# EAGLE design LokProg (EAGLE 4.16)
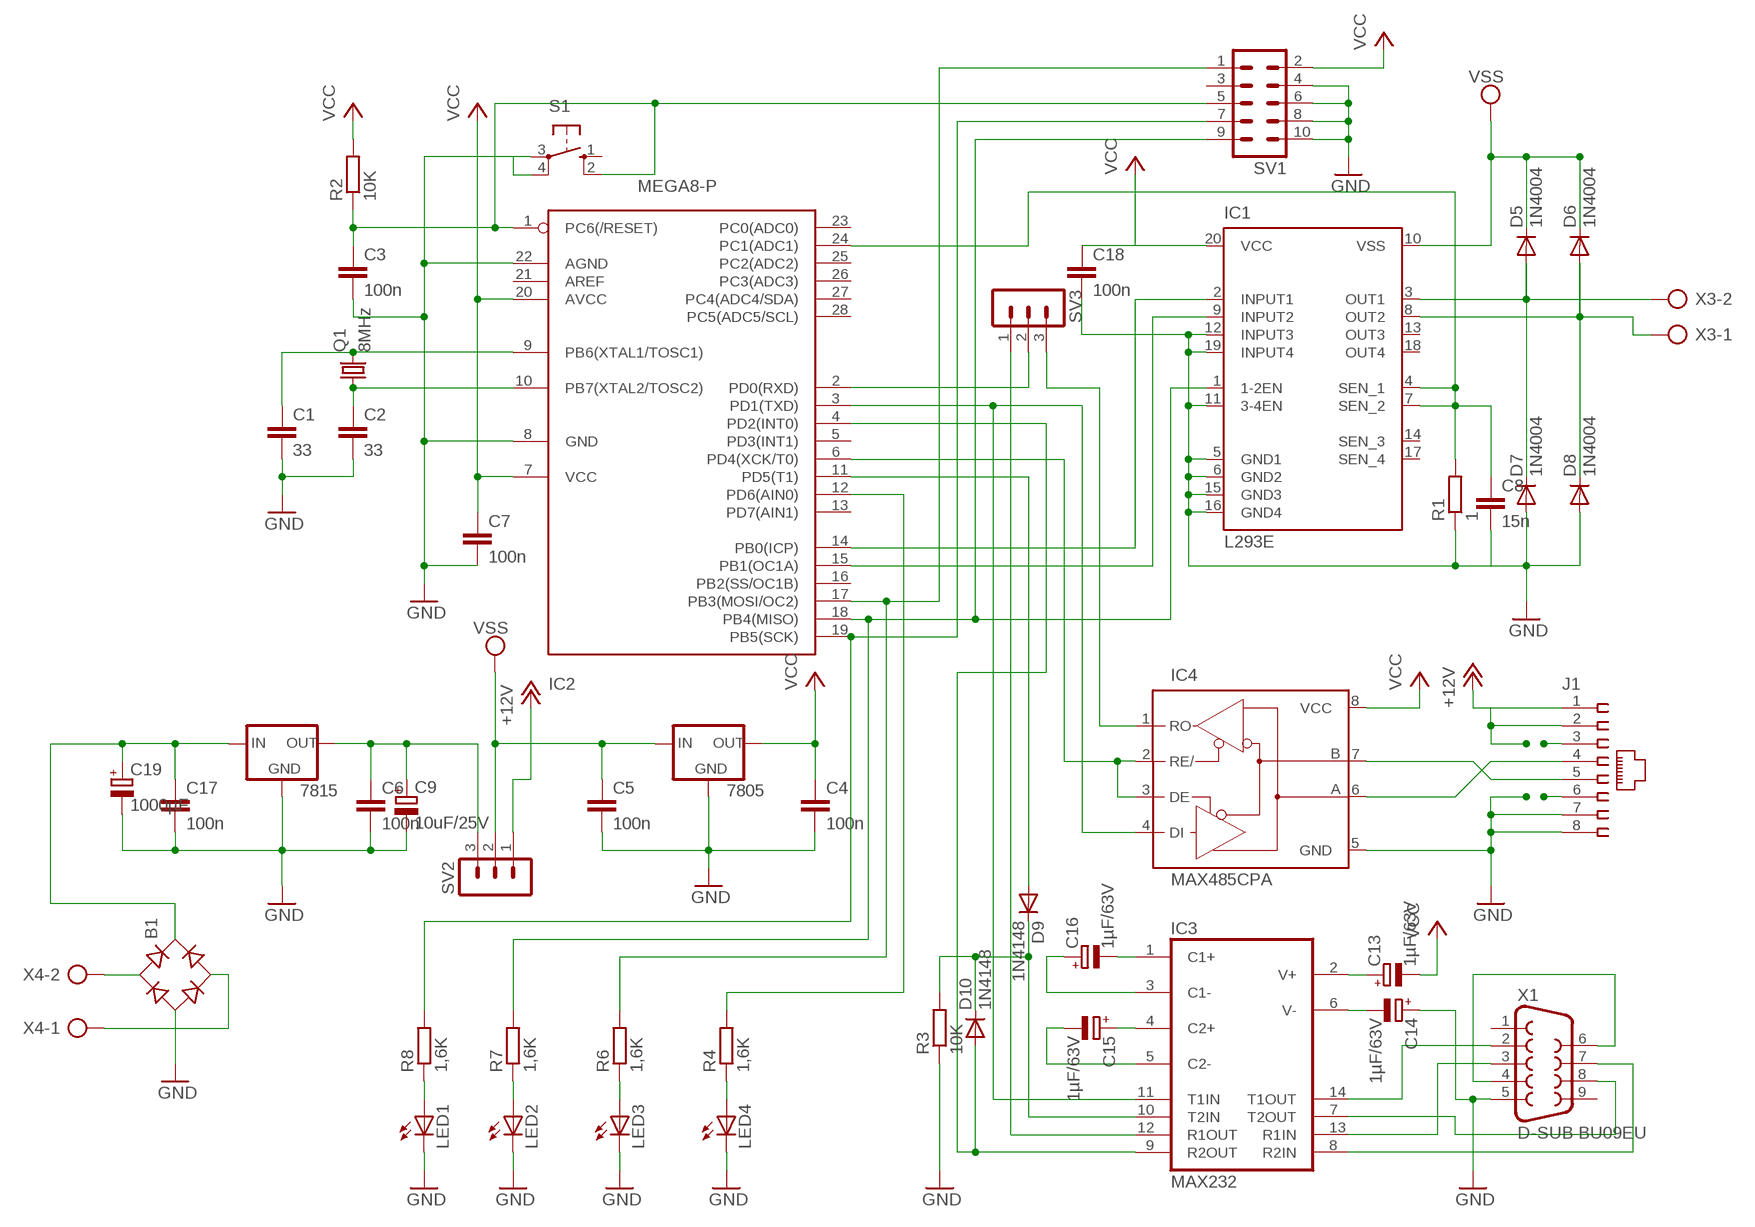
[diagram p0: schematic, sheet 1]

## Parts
7805  78XXL  [78XXL]
7815  78XXL  [78XXL]
B1  RB1A  [RB1A]
C1  33  C-EU025-025X050  [C025-025X050]
C2  33  C-EU025-025X050  [C025-025X050]
C3  100n  C-EU025-025X050  [C025-025X050]
C4  100n  C-EU025-025X050  [C025-025X050]
C5  100n  C-EU025-025X050  [C025-025X050]
C6  100n  C-EU025-025X050  [C025-025X050]
C7  100n  C-EU025-025X050  [C025-025X050]
C8  15n  C-EU025-025X050  [C025-025X050]
C9  10uF/25V  CPOL-EUE2.5-5  [E2,5-5]
C13  1µF/63V  CPOL-EUE2.5-5  [E2,5-5]
C14  1µF/63V  CPOL-EUE2.5-5  [E2,5-5]
C15  1µF/63V  CPOL-EUE2.5-5  [E2,5-5]
C16  1µF/63V  CPOL-EUE2.5-5  [E2,5-5]
C17  100n  C-EU025-025X050  [C025-025X050]
C18  100n  C-EU025-025X050  [C025-025X050]
C19  1000µF  CPOL-EUE35-14AXIAL  [E35-14]
D5  1N4004  [DO41-10]
D6  1N4004  [DO41-10]
D7  1N4004  [DO41-10]
D8  1N4004  [DO41-10]
D9  1N4148  [DO35-10]
D10  1N4148  [DO35-10]
IC1  L293E  [DIL20]
IC2  MEGA8-P  [DIL28-3]
IC3  MAX232  [DIL16]
IC4  MAX485CPA  MAX3468CPA  [DIL08]
J1  555166-1  [555166-1]
LED1  LED3MM  [LED3MM]
LED2  LED3MM  [LED3MM]
LED3  LED3MM  [LED3MM]
LED4  LED3MM  [LED3MM]
Q1  8MHz  CRYSTALHC49U70  [HC49U70]
R1  1  R-EU_0207/10  [0207/10]
R2  10K  R-EU_0207/10  [0207/10]
R3  10K  R-EU_0207/10  [0207/10]
R4  1,6K  R-EU_0207/10  [0207/10]
R6  1,6K  R-EU_0207/10  [0207/10]
R7  1,6K  R-EU_0207/10  [0207/10]
R8  1,6K  R-EU_0207/10  [0207/10]
S1  10-XX  [B3F-10XX]
SV1  ML10  [ML10]
SV2  MA03-1  [MA03-1]
SV3  MA03-1  [MA03-1]
X1  D-SUB BU09EU  F09HP  [F09HP]
X3  AK500/2-H  [AK500/2-H]
X4  AK500/2-H  [AK500/2-H]

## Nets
+12V: J1.1 J1.2 SV2.1
GND: 7805.GND 7815.GND B1.- C1.2 C2.2 C3.2 C4.2 C5.2 C6.2 C7.2 C8.2 C9.- C14.+ C17.2 C18.2 C19.- D7.A D8.A IC1.5(GND1) IC1.6(GND2) IC1.11(3-4EN) IC1.12(INPUT3) IC1.15(GND3) IC1.16(GND4) IC1.19(INPUT4) IC2.8(GND) IC2.22(AGND) IC4.5(GND) J1.7 J1.8 LED1.K(C) LED2.K(C) LED3.K(C) LED4.K(C) R1.1 R3.1 S1.3(P) S1.4(P1) SV1.4 SV1.6 SV1.8 SV1.10 X1.5
N$1: D5.A D7.C IC1.3(OUT1) X3.2
N$2: D6.A D8.C IC1.8(OUT2) X3.1
N$3: J1.6
N$4: 7815.IN B1.+ C17.1 C19.+
N$5: IC1.1(1-2EN) IC2.18(PB4(MISO)) R7.2 SV1.9
N$6: IC1.9(INPUT2) IC2.15(PB1(OC1A))
N$7: IC1.2(INPUT1) IC2.14(PB0(ICP))
N$8: C8.1 IC1.4(SEN_1) IC1.7(SEN_2) IC2.24(PC1(ADC1)) R1.2
N$9: J1.3
N$10: IC3.12(R1OUT) SV3.1
N$11: IC4.6(A) J1.4
N$12: IC4.7(B) J1.5
N$13: IC2.3(PD1(TXD)) IC3.11(T1IN) IC4.4(DI)
N$14: IC2.6(PD4(XCK/T0)) IC4.2(RE/) IC4.3(DE)
N$15: IC2.2(PD0(RXD)) SV3.2
N$16: C1.1 IC2.9(PB6(XTAL1/TOSC1)) Q1.2
N$17: C2.1 IC2.10(PB7(XTAL2/TOSC2)) Q1.1
N$18: IC3.13(R1IN) X1.3
N$19: C3.1 IC2.1(PC6(/RESET)) R2.1 S1.2(S1) SV1.5
N$20: X1.4 X1.6
N$21: IC3.8(R2IN) X1.7
N$22: IC3.14(T1OUT) X1.2
N$23: IC3.7(T2OUT) X1.8
N$24: C16.- IC3.1(C1+)
N$25: C16.+ IC3.3(C1-)
N$26: C15.+ IC3.4(C2+)
N$27: C15.- IC3.5(C2-)
N$28: C13.+ IC3.2(V+)
N$29: C14.- IC3.6(V-)
N$30: IC2.17(PB3(MOSI/OC2)) R6.2 SV1.1
N$31: IC2.19(PB5(SCK)) R8.2 SV1.7
N$32: IC4.1(RO) SV3.3
N$33: LED4.A R4.1
N$35: LED3.A R6.1
N$36: D9.A IC2.11(PD5(T1))
N$37: D9.C D10.C IC3.10(T2IN) R3.2
N$38: D10.A IC2.4(PD2(INT0)) IC3.9(R2OUT)
N$39: LED2.A R7.1
N$40: IC2.12(PD6(AIN0)) R4.2
N$41: LED1.A R8.1
N$42: 7815.OUT C6.1 C9.+ SV2.3
N$43: B1.AC1 X4.2
N$44: B1.AC2 X4.1
VCC: 7805.OUT C4.1 C7.1 C13.- C18.1 IC1.20(VCC) IC2.7(VCC) IC2.20(AVCC) IC4.8(VCC) R2.2 SV1.2
VSS: 7805.IN C5.1 D5.C D6.C IC1.10(VSS) SV2.2
Unconnected: IC1.13(OUT3) IC1.14(SEN_3) IC1.17(SEN_4) IC1.18(OUT4) IC2.5(PD3(INT1)) IC2.13(PD7(AIN1)) IC2.16(PB2(SS/OC1B)) IC2.21(AREF) IC2.23(PC0(ADC0)) IC2.25(PC2(ADC2)) IC2.26(PC3(ADC3)) IC2.27(PC4(ADC4/SDA)) IC2.28(PC5(ADC5/SCL)) S1.1(S) SV1.3 X1.1 X1.9

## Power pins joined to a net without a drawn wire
GND: IC3.15(GND)
VCC: IC3.16(VCC)

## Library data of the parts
7805 7815 = v-reg:78XXL: VOLTAGE REGULATOR
B1 = rectifier:RB1A: RECTIFIER 1 A
C1-C8 C17 C18 = rcl:C-EU: CAPACITOR, European symbol
C9 C13-C16 C19 = rcl:CPOL-EU: POLARIZED CAPACITOR, European symbol
D5-D8 = diode:1N4004: DIODE
D9 D10 = diode:1N4148: DIODE
IC1 = l293e:L293E: PUSH-PULL 4 CHANNEL DRIVER
IC2 = atmel:MEGA8-P: MICROCONTROLLER 8 Kbytes FLASH 1 kbytes SRAM 512 bytes EEPROM USART 4-channel 10 bit ADC 2-channel 8 bit ADC Source: avr.lbr
IC3 = maxim:MAX232: RS232 TRANSEIVER
IC4 = maxim:MAX34*: +5V, Fail-Safe, 40Mbps, Profibus RS-485/RS-422 Transceivers Source: MAX3465-MAX3469.pdf
J1 = con-amp:555166-1: AMP connector
LED1-LED4 = led:LED: LED
Q1 = crystal:CRYSTAL: CRYSTAL
R1-R4 R6-R8 = rcl:R-EU_: RESISTOR, European symbol
S1 = switch-omron:10-XX: OMRON SWITCH
SV1 = con-harting-ml:ML10: HARTING
SV2 SV3 = con-lstb:MA03-1: PIN HEADER
X1 = con-subd:F09: SUB-D
X3 X4 = con-ptr500:AK500/2-H: CONNECTOR

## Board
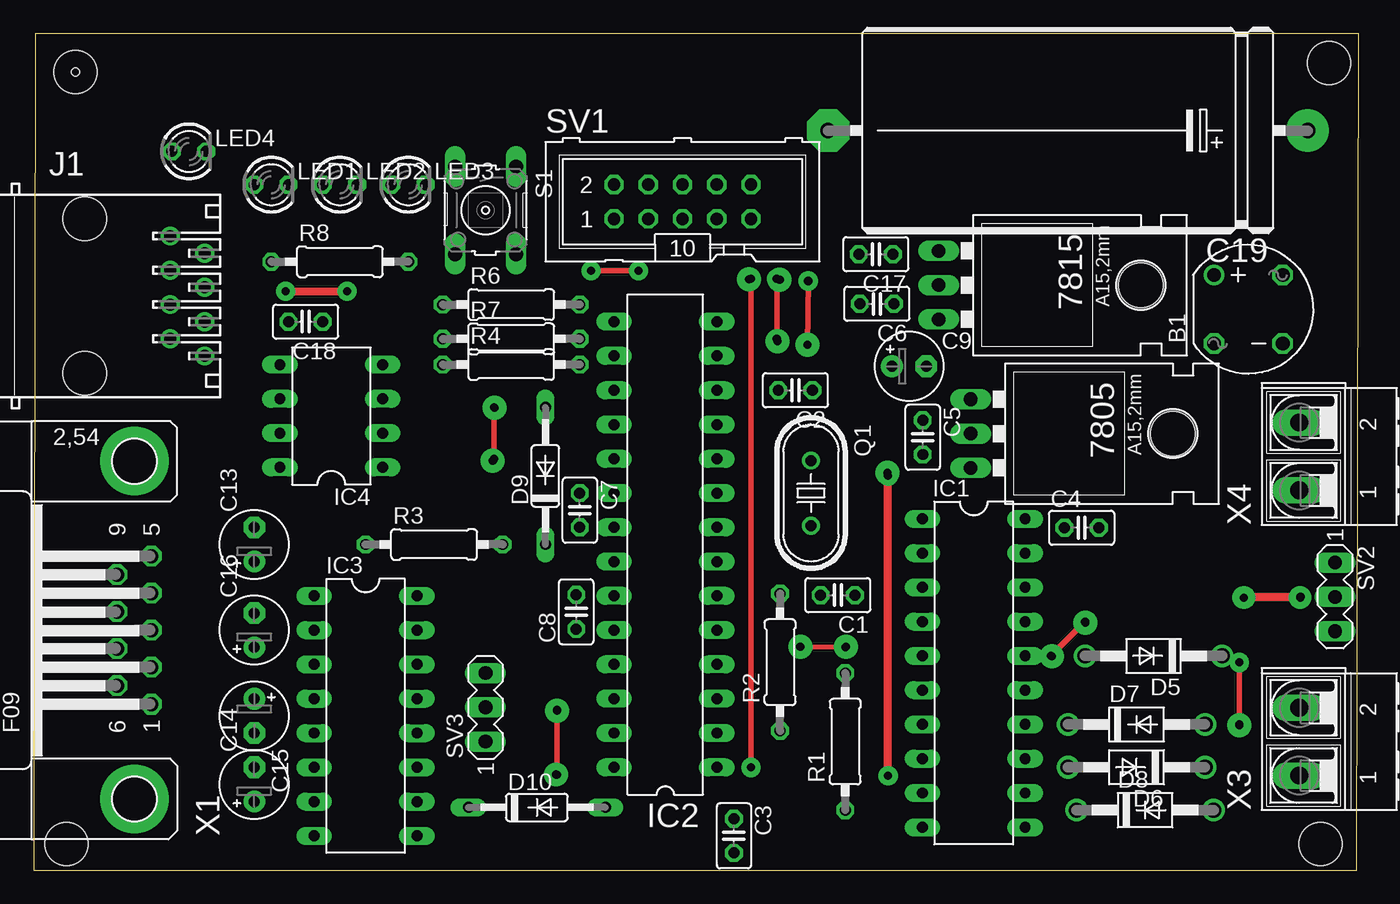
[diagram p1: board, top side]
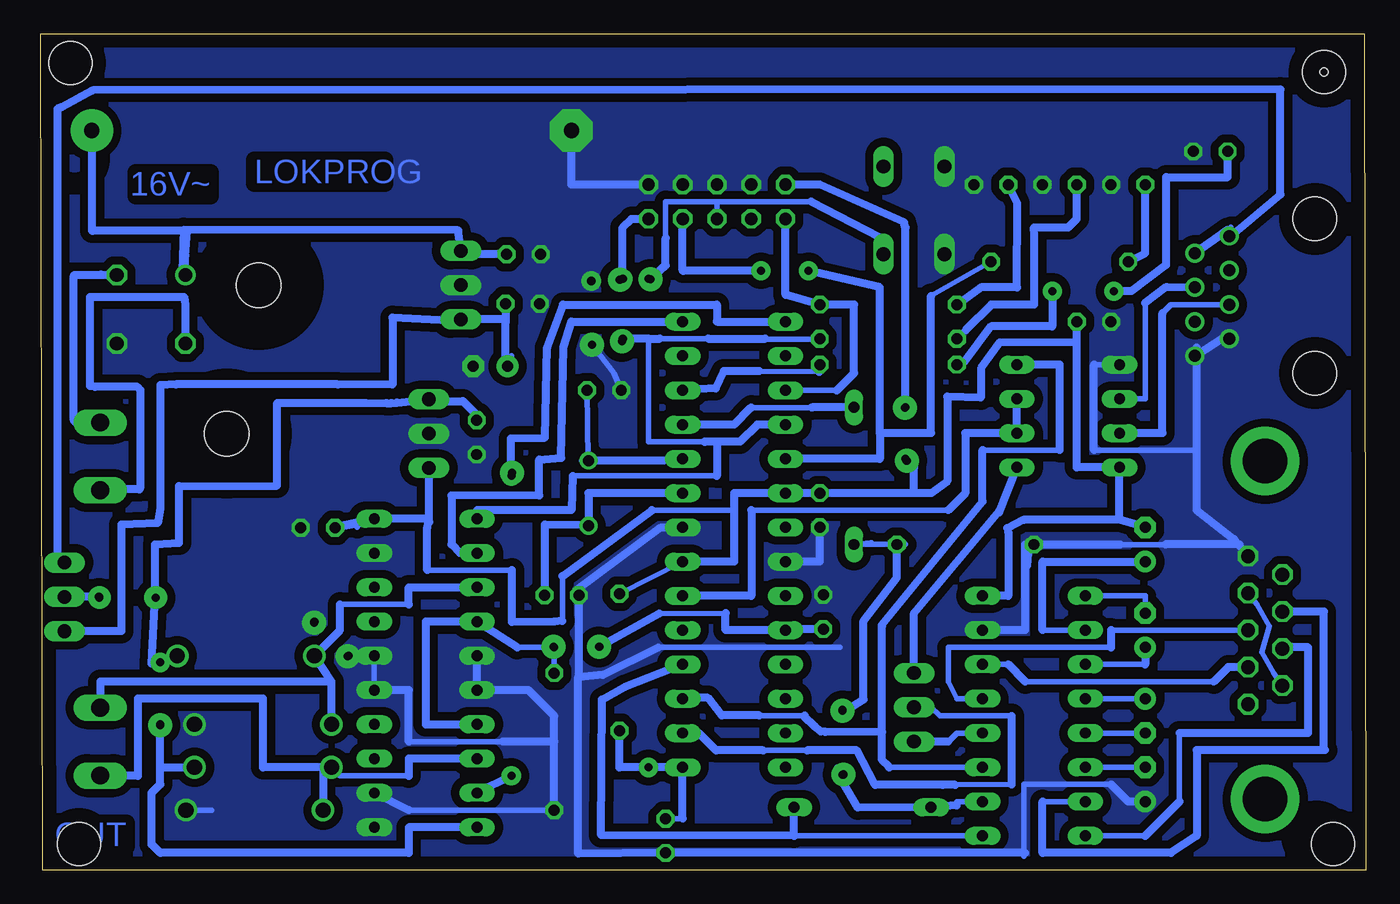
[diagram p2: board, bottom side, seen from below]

Size 98.22 x 61.97 mm. Coordinates in mm from the lower left corner, seen from the top.
Outline: 0,0 98.09,0 98.22,61.97 0.12,61.97 0,0
Copper layers (1*16): Top 0.035mm / dielectric 1.5mm / Bottom 0.035mm
Design rules "default": minimum track width 0.4mm, minimum drill 0.6mm, track to track 8mil, track to pad 8mil, pad to pad 8mil, via to via 8mil, smd to smd 8mil, copper to edge 40mil, drill to drill 8mil, minimum pad ring 10mil, minimum via ring 8mil, stop-mask expansion 4mil, vias tented up to drill 0mil, thermal gap 10mil
Holes 0.6 mm at 3.08,59.14 3.08,59.14
Holes 3.2 mm at 3.08,59.14 96.03,59.79 95.38,1.95 2.44,1.95
bRestrict: area 1.8,0.7 to 5.4,4.3; area 93.9,50.9 to 97.5,54.5

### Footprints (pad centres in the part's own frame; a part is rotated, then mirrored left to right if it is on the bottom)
78XXL = drill 1.016 long: GND 0,-3.81; IN -2.54,-3.81; OUT 2.54,-3.81 | hole 3.302: 0,11.176
RB1A = drill 1.016 round: + -2.54,2.54 | drill 1.016 octagon: - 2.54,-2.54; AC1 2.54,2.54; AC2 -2.54,-2.54
C025-025X050 = drill 0.813 octagon: 1 -1.27,0; 2 1.27,0
E2,5-5 = drill 0.813 pad 1.6 round: + -1.27,0 | drill 0.813 pad 1.6 octagon: - 1.27,0
E35-14 = drill 1.118 pad 3.15 round: + -17.78,0 | drill 1.118 pad 3.15 octagon: - 17.78,0
DO41-10 = drill 1.118 round: A 5.08,0; C -5.08,0
DO35-10 = drill 0.813 long: A 5.08,0; C -5.08,0
DIL20 = drill 0.813 long: 1 -11.43,-3.81; 2 -8.89,-3.81; 3 -6.35,-3.81; 4 -3.81,-3.81; 5 -1.27,-3.81; 6 1.27,-3.81; 7 3.81,-3.81; 8 6.35,-3.81; 9 8.89,-3.81; 10 11.43,-3.81; 11 11.43,3.81; 12 8.89,3.81; 13 6.35,3.81; 14 3.81,3.81; 15 1.27,3.81; 16 -1.27,3.81; 17 -3.81,3.81; 18 -6.35,3.81; 19 -8.89,3.81; 20 -11.43,3.81
DIL28-3 = drill 0.813 long: 1 -16.51,-3.81; 2 -13.97,-3.81; 3 -11.43,-3.81; 4 -8.89,-3.81; 5 -6.35,-3.81; 6 -3.81,-3.81; 7 -1.27,-3.81; 8 1.27,-3.81; 9 3.81,-3.81; 10 6.35,-3.81; 11 8.89,-3.81; 12 11.43,-3.81; 13 13.97,-3.81; 14 16.51,-3.81; 15 16.51,3.81; 16 13.97,3.81; 17 11.43,3.81; 18 8.89,3.81; 19 6.35,3.81; 20 3.81,3.81; 21 1.27,3.81; 22 -1.27,3.81; 23 -3.81,3.81; 24 -6.35,3.81; 25 -8.89,3.81; 26 -11.43,3.81; 27 -13.97,3.81; 28 -16.51,3.81
DIL16 = drill 0.813 long: 1 -8.89,-3.81; 2 -6.35,-3.81; 3 -3.81,-3.81; 4 -1.27,-3.81; 5 1.27,-3.81; 6 3.81,-3.81; 7 6.35,-3.81; 8 8.89,-3.81; 9 8.89,3.81; 10 6.35,3.81; 11 3.81,3.81; 12 1.27,3.81; 13 -1.27,3.81; 14 -3.81,3.81; 15 -6.35,3.81; 16 -8.89,3.81
DIL08 = drill 0.813 long: 1 -3.81,-3.81; 2 -1.27,-3.81; 3 1.27,-3.81; 4 3.81,-3.81; 5 3.81,3.81; 6 1.27,3.81; 7 -1.27,3.81; 8 -3.81,3.81
555166-1 = drill 0.889 round: 1 -4.445,5.207; 2 -3.175,7.747; 3 -1.905,5.207; 4 -0.635,7.747; 5 0.635,5.207; 6 1.905,7.747; 7 3.175,5.207; 8 4.445,7.747 | hole 3.251: -5.715,-1.143; 5.715,-1.143
LED3MM = drill 0.813 octagon: A -1.27,0; K 1.27,0
HC49U70 = drill 0.813 round: 1 -2.413,0; 2 2.413,0
0207/10 = drill 0.813 octagon: 1 -5.08,0; 2 5.08,0
B3F-10XX = drill 1.016 long: 1 -3.251,2.261; 2 3.251,2.261; 3 -3.251,-2.261; 4 3.251,-2.261
ML10 = drill 0.914 octagon: 1 -5.08,-1.27; 2 -5.08,1.27; 3 -2.54,-1.27; 4 -2.54,1.27; 5 0,-1.27; 6 0,1.27; 7 2.54,-1.27; 8 2.54,1.27; 9 5.08,-1.27; 10 5.08,1.27
MA03-1 = drill 1.016 long: 1 -2.54,0; 2 0,0; 3 2.54,0
F09HP = drill 1.016 octagon: 1 -5.486,-1.27; 2 -2.743,-1.27; 3 0,-1.27; 4 2.743,-1.27; 5 5.486,-1.27; 6 -4.115,1.27; 7 -1.372,1.27; 8 1.372,1.27; 9 4.115,1.27 | drill 3.302 pad 5.08 round: G1 -12.522,0; G2 12.522,0
AK500/2-H = drill 1.321 long: 1 -2.515,0; 2 2.515,0

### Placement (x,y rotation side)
7805  73.26,32.34 270 top
7815  70.89,43.34 270 top
B1  90.05,41.57 0 top
C1  59.61,20.37 180 top
C2  56.46,35.55 180 top
C3  51.91,2.54 270 top
C4  77.68,25.37 0 top
C5  65.9,32.06 270 top
C6  62.5,41.96 180 top
C7  40.48,26.67 270 top
C8  40.22,19.13 90 top
C9  64.89,37.33 0 top
C13  16.35,24.12 90 top
C14  16.35,6.34 90 top
C15  16.35,11.42 270 top
C16  16.35,17.78 90 top
C17  62.43,45.63 180 top
C18  20.16,40.63 180 top
C19  76.66,54.8 180 top
D5  83.02,15.87 180 top
D6  81.75,7.62 180 top
D7  81.75,10.79 0 top
D8  82.38,4.44 0 top
D9  37.94,29.21 90 top
D10  37.3,4.65 0 top
IC1  69.68,14.6 270 top
IC2  46.83,24.12 90 top
IC3  24.6,11.42 270 top
IC4  22.06,33.65 90 top
J1  4.92,42.54 270 top
LED1  17.62,50.79 0 top
LED2  22.7,50.79 0 top
LED3  27.78,50.79 0 top
LED4  11.51,53.25 0 top
Q1  57.62,27.94 270 top
R1  60.16,9.52 90 top
R2  55.33,15.4 90 top
R3  29.68,24.12 0 top
R4  35.4,37.46 0 top
R6  35.4,41.9 0 top
R7  35.4,39.36 0 top
R8  22.7,45.08 0 top
S1  33.49,48.89 270 top
SV1  48.09,49.52 0 top
SV2  96.46,20.24 270 top
SV3  33.49,12.06 90 top
X1  7.46,17.78 90 top
X3  93.81,9.52 90 top
X4  93.81,30.65 90 top

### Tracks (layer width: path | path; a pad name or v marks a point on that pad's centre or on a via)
+12V
  Bottom 0.4: J1.1 10,47.62 | 96.99,22.84 96.73,22.77
  Bottom 0.406: 96.99,22.84 SV2.1
  Bottom 0.61: 96.99,22.84 96.99,56.4 96.68,56.54 94.38,57.78 6.33,57.84 6.33,50.04 10.24,46.79 J1.1 10.24,47.45 J1.2
GND  (via drill 0.6 pad 1.42, 0.6 pad 1.78)
  Top 0.406: v57.36,38.92 v57.41,43.65 | v75.4,15.87 v77.94,18.41
  Bottom 0.406: 18.89,6.34 25.23,6.34 25.36,6.34 25.36,1.27 25.36,1.01 | J1.7 10.63,39.36 | IC1.15 IC1.16 v75.4,15.87 | R1.1 70.95,4.44 | 52.44,16.51 38.98,16.51 | 58.39,14.3 56.56,14.47 | 20.16,37.46 IC4.5 | 12.54,31.11 20.16,31.11 | 9.36,24.12 9.4,24.09 | C1.2 58.6,20.65 | C2.2 55.72,36.82 v57.36,38.92 | 85.56,4.44 D8.A | IC1.5 65.24,15.87 | 63.34,9.52 63.97,9.52 70.95,9.52 | 14.86,24.12 18.23,24.12
  Bottom 0.61: C14.+ 17.62,5.08 18.89,6.34 | 10.63,39.36 12.54,38.14 | X1.5 9.4,24.09 9.77,24.53 12.54,26.67 12.54,31.11 12.54,38.73 | R1.1 60.16,9.52 | 60.16,9.52 60.16,11.42 62.06,13.33 IC1.6 IC1.5 | 70.95,4.44 IC1.12 | IC2.22 40.48,22.86 C7.2 | 52.44,16.51 56.56,14.47 58.34,14.27 C1.2 | SV1.10 58.89,50.79 C19.- | 20.16,31.11 20.16,37.46 | 29.05,17.78 25.23,17.78 25.23,24.12 | IC2.8 52.24,25.39 58.6,20.65 | 58.39,14.3 58.39,1.21 C3.2 25.36,1.27 25.23,1.27 | 70.95,9.52 70.95,13.33 IC1.15 | 60.16,9.52 63.97,9.52 | 9.36,24.12 14.86,24.12 | 25.02,23.95 25.11,22.56 | 25.02,23.95 R3.1 | 18.23,24.12 24.68,24.12 25.02,23.95
  other vias: 57.37,38.93 75.47,15.84 77.96,18.34
  pour Bottom (isolate 0.61, no thermals): -0.29,62.74 98.76,62.85 98.26,-0.64 -0.17,-0.64
N$1
  Bottom 0.406: 76.03,19.68 70.95,19.68
  Bottom 0.61: IC1.3 70.95,20.95 70.95,19.68 | 76.03,19.68 76.03,17.78 D5.A 76.67,13.96 | D7.C 76.67,13.96 | 76.67,13.96 93.81,13.96 X3.2
N$2
  Bottom 0.406: 70.95,6.98 76.03,6.98 D6.A 77.3,7.62
  Bottom 0.61: IC1.8 70.95,8.25 70.95,6.98 | X3.1 91.93,7 91.02,6.98 91.02,12.69 81.75,12.69 81.75,7.62 77.3,7.62 D8.C
N$4
  Bottom 0.61: 67.1,45.88 67.22,46 | 67.1,45.88 7815.IN 67.27,47.4 87.63,47.43 87.75,44.43 87.43,44.1 | C17.1 66.85,45.63 67.1,45.88 | 87.43,44.1 87.38,44.05 | 87.43,44.1 B1.+ 87.51,45.53 87.36,47.37 94.39,47.37 94.43,47.4 94.43,54.86 94.44,54.84 C19.+
N$5  (via drill 0.6 pad 1.42, 0.6 pad 1.78)
  Top 0.406: v55.08,39.36 v55.08,43.81
  Bottom 0.4: IC2.18 44.29,33.02 | 55.05,39.33 55.1,39.25 | v55.15,39.18 55.05,39.33 | 55.05,39.33 v55.08,39.36 | 55.08,44.45 v55.07,43.8 v55.3,43.75 | 53.18,39.36 53.18,39.38
  Bottom 0.406: 48.11,29.21 58.79,29.21 | 65.88,26.67 IC1.1 | 48.09,31.75 49,31.75 53.18,31.75 53.18,39.36 | R7.2 40.6,39.36 40.62,39.34 44.47,39.34 44.51,39.38 | 52.33,39.38 48.76,39.38
  Bottom 0.61: 44.29,33.02 45.11,33.02 46.38,31.75 49,31.75 49,31.7 | 48.09,31.75 48.11,29.21 | 58.79,29.21 58.89,26.67 65.88,26.67 | v55.08,43.81 55.08,44.45 55.08,47.62 54.45,48.25 SV1.9 | 55.1,39.25 55.03,39.18 | 48.76,39.38 44.51,39.38 | v55.15,39.18 v55.14,39.18 55.11,39.14 54.87,39.38 53.18,39.38 52.33,39.38
N$6  (via drill 0.6 pad 1.42, 0.6 pad 1.78)
  Top 0.61: v63.34,6.98 v63.34,29.21
  Bottom 0.4: v63.34,29.21 v63.29,29.43
  Bottom 0.61: IC2.15 48.09,40.63 48.09,41.9 59.52,41.9 60.68,38.73 60.85,32.04 63.38,31.98 63.38,29.58 v63.34,29.21 | v63.34,6.98 IC1.9
N$7
  Bottom 0.406: 67.14,23.49 IC1.2
  Bottom 0.61: IC2.14 58.89,40.63 59.49,38.73 59.65,30.54 61.28,30.41 61.28,27.76 67.78,27.74 67.78,24.12 67.14,23.49
N$8  (via drill 0.6 pad 1.42, 0.6 pad 1.78)
  Top 0.406: v56.81,16.54 v60.16,16.51
  Bottom 0.4: 52.39,18.99 v56.85,16.53 | v60.16,16.51 60.8,16.51 v60.23,16.54
  Bottom 0.406: 47.46,19.05 52.39,18.99 | 42.93,17.86 IC2.24 | 62.91,16.5 v60.16,16.51 R1.2
  Bottom 0.61: IC1.7 69.68,10.79 69.68,18.41 IC1.4 62.91,16.5 | IC2.24 47.46,17.78 47.46,19.05 | 52.39,18.99 v56.81,16.54 | C8.1 42.93,17.86
N$10
  Bottom 0.4: IC3.12 30.32,10.15
  Bottom 0.406: 30.32,10.15 30.95,9.52
  Bottom 0.61: 30.95,9.52 SV3.1
N$11
  Bottom 0.406: 16.35,42.04 16.35,34.92 IC4.6
  Bottom 0.61: 16.35,42.04 14.77,43.22 J1.4
N$12
  Bottom 0.406: 15.08,41.27 14.44,41.9 J1.5
  Bottom 0.61: 15.08,41.27 15.08,32.38 IC4.7
N$13
  Bottom 0.4: IC3.11 35.4,7.62 35.36,7.65
  Bottom 0.406: 28.41,31.11 22.7,31.11 | 41.59,11.44 45.07,11.44 44.95,11.47
  Bottom 0.61: IC4.4 22.7,37.46 22.7,31.11 | 28.41,31.11 28.41,27.3 35.85,18.17 35.85,18.16 35.89,18.12 35.86,18.09 35.86,10.22 | 44.95,11.47 47.75,11.47 48.78,12.76 50.54,12.76 50.61,12.69 50.62,12.69 IC2.3 | 35.33,7.62 35.36,7.65 35.86,8.14 35.86,10.22 | 41.59,11.44 41.63,11.38 40.86,10.67 40.4,10.28 40.07,10.25 35.86,10.22
N$14
  Bottom 0.406: 30.95,26.67 45.55,26.67
  Bottom 0.61: IC4.3 IC4.2 29.68,32.38 29.68,27.94 30.95,26.67 | 45.55,26.67 45.55,20.32 IC2.6
N$15
  Bottom 0.406: SV3.2 32.22,12.06 31.59,11.42 26.25,11.42 | 26.25,6.34 30.43,6.31 | 44.68,8.87 44.68,8.84 44.64,8.87 41.41,8.87
  Bottom 0.61: 26.25,6.34 26.25,11.42 | 30.43,6.31 31.35,6.31 36.38,6.31 37.72,8.87 41.41,8.87 | IC2.2 49.43,10.15 48.15,8.87 44.68,8.87
N$16
  Bottom 0.406: Q1.2 57.25,25.57
  Bottom 0.61: Q1.2 57.62,27.94 IC2.9 | 57.25,25.57 60.87,25.59 C1.1
N$17
  Bottom 0.406: 52.03,30.35 IC2.10 | Q1.1 58.13,30.35 57.66,30.4 C2.1
  Bottom 0.61: 52.03,30.35 Q1.1
N$18
  Bottom 0.4: 30.32,12.69 IC3.13
  Bottom 0.406: X1.3 18.89,17.78 | 18.89,16.51 30.95,16.51 30.95,13.96 30.32,12.69
  Bottom 0.61: 18.89,17.78 18.89,16.51
N$19  (via drill 0.6 pad 1.42, 0.6 pad 1.78)
  Top 0.406: v53.18,7.6 v53.18,43.81
  Bottom 0.4: 53.18,43.77 v53.18,43.81 53.18,43.78 v53.03,43.77
  Bottom 0.406: C3.1 50.63,3.81 | 48.09,49.52 41.11,49.52 | 48.09,49.52 SV1.5 | 48.09,49.52 51.91,49.52 51.91,46.83 | S1.2 36.11,45.64 36.03,45.71 36.11,45.79 36.11,46.92
  Bottom 0.61: 50.63,3.81 IC2.1 v53.18,7.6 55.33,7.6 R2.1 | 41.11,49.52 36.11,46.92 | 51.91,46.83 51.91,44.8 52.01,44.7 52.05,44.7 52.94,43.81 v53.18,43.81
N$20
  Bottom 0.406: X1.4 8.09,19.7 7.13,18.07 7.72,16.16 6.82,14.6 X1.6
N$21
  Bottom 0.4: 16.35,2.54 IC3.8
  Bottom 0.406: 13.81,10.15 13.81,5.08 | 6.18,16.51 X1.7
  Bottom 0.61: 13.81,5.08 16.35,2.54 | 13.81,10.15 4.28,10.15 4.28,16.51 6.18,16.51
N$22
  Bottom 0.4: 26.51,15.23 IC3.14
  Bottom 0.406: 11.27,13.96 25.23,13.96
  Bottom 0.61: X1.2 10.2,15.03 11.27,13.96 | 25.23,13.96 26.51,15.23
N$23
  Bottom 0.4: 23.96,5.08 IC3.7
  Bottom 0.406: 3.01,8.88 3.11,8.99
  Bottom 0.61: X1.8 3.11,19.15 3.11,8.99 | 23.96,5.08 23.96,1.27 14.44,1.27 12.54,2.54 12.54,8.88 3.01,8.88
N$24
  Bottom 0.4: 16.35,20.32 IC3.1
  Bottom 0.406: C16.- 16.35,20.32
N$25
  Bottom 0.4: 16.35,15.23 IC3.3
  Bottom 0.61: C16.+ 16.35,15.23
N$26
  Bottom 0.4: C15.+ IC3.4
N$27
  Bottom 0.4: C15.- IC3.5
N$28
  Bottom 0.4: IC3.2 23.96,17.78
  Bottom 0.61: C13.+ 23.96,22.86 23.96,17.78
N$29
  Bottom 0.4: C14.- IC3.6
N$30
  Bottom 0.406: 41.74,35.55 IC2.17 39.2,35.55
  Bottom 0.61: 39.2,35.55 37.94,36.82 37.94,41.9 R6.2 43.02,42.62 SV1.1
N$31  (via drill 0.6 pad 1.42)
  Top 0.406: v41.32,44.41 v44.84,44.41
  Bottom 0.406: 32.22,42.54 R8.2
  Bottom 0.61: IC2.19 36.03,30.48 36.03,32.38 | 36.03,32.38 36.03,43.17 v41.32,44.41 | SV1.7 50.63,44.45 50.6,44.41 v44.84,44.41 | 32.22,42.54 32.22,32.38 36.03,32.38
N$32
  Bottom 0.406: 27.14,26.67 27.18,26.49
  Bottom 0.61: 27.18,26.49 IC4.1 | 27.14,26.67 33.49,19.05 SV3.3
N$33  (via drill 0.6 pad 1.42)
  Top 0.61: v18.69,42.89 v23.23,42.89
  Bottom 0.406: 10.24,51.34 10.24,51.35 | R4.1 30.39,37.7 29.73,37.7
  Bottom 0.61: 10.24,51.35 LED4.A | 10.24,51.34 14.79,51.34 14.79,44.84 17.39,42.89 v18.69,42.89 | 29.73,37.7 27.79,40.29 23.23,40.29 v23.23,42.89
N$35
  Bottom 0.61: R6.1 28.55,43.17 25.86,43.17 25.84,49.39 LED3.A
N$36
  Bottom 0.406: 45.63,34.21 45.59,34.16 45.49,34.26 41.08,34.26 | 45.63,34.21
  Bottom 0.61: 45.55,34.28 45.63,34.21 46.83,33.02 IC2.11 | D9.A 41.05,34.28 41.08,34.26
N$37  (via drill 0.6 pad 1.42, 0.6 pad 1.78)
  Top 0.406: v38.78,7.07 v38.8,11.88
  Bottom 0.4: R3.2 36.66,24.12 36.68,24.27 | v38.73,7.08 39.2,7.62 v38.78,7.07 | v38.8,11.88 39.2,11.42 v38.79,11.79 | IC3.10 30.32,5.08 30.32,4.8
  Bottom 0.406: 36.66,24.27 36.68,24.27 D9.C R3.2 34.12,24.12
  Bottom 0.61: 30.32,4.8 D10.C 37.66,4.63 38.75,6.52 v38.78,7.07 | v38.8,11.88 38.47,11.88 37.23,12.66 37.23,18.46 34.76,21.69 R3.2
N$38
  Bottom 0.4: IC3.9 42.38,2.54
  Bottom 0.61: IC2.4 54.92,13.57 56.62,12.62 56.69,2.59 42.38,2.54 D10.A
N$39
  Bottom 0.406: 29.67,40 R7.1
  Bottom 0.61: 29.67,40 27.77,41.9 24.59,41.9 24.59,46.98 24.6,47.62 22.06,47.62 21.43,48.25 LED2.A
N$40
  Bottom 0.406: 40.53,36.91 44.95,36.98
  Bottom 0.61: IC2.12 48.19,35.68 47.6,36.98 44.95,36.98 | R4.2 40.55,37.46 40.79,37.7 40.53,36.91
N$41
  Bottom 0.61: R8.1 16.35,45.71 LED1.A
N$42
  Bottom 0.4: 63.72,37.6 63.34,38.09 C9.+
  Bottom 0.61: C9.+ 63.62,37.6 63.77,37.75 63.77,40.6 | 63.77,40.6 63.77,40.75 63.92,40.75 63.97,40.8 7815.OUT | SV2.3 92.26,17.7 92.25,17.71 92.25,25.59 89.57,25.72 89.37,26.78 89.37,35.94 88.2,35.99 76.21,35.99 72.14,35.97 72.14,40.93 67.22,40.67 7815.OUT | 7815.OUT 67.07,40.82 | 63.77,40.6 63.75,40.6 63.75,41.96 C6.1 | 63.72,37.6 63.72,37.33
N$43
  Bottom 0.61: 93.73,44.1 B1.AC1 | 93.73,44.1 93.75,44.13 | 93.73,44.1 95.72,44.1 95.77,44.05 95.77,33.32 95.55,33.09 93.68,33.09 93.74,33.16 X4.2
N$44
  Bottom 0.61: B1.AC2 87.51,41.9 87.6,42.48 94.57,42.48 94.57,35.87 94.2,35.8 91.05,35.8 90.83,35.57 90.83,28.44 90.9,28.22 93.9,28.22 X4.1
VCC  (via drill 0.6 pad 1.42, 0.6 pad 1.78)
  Top 0.406: v34.12,30.48 v34.12,34.28
  Bottom 0.4: v34.12,30.48 v34.03,30.33 | v34.12,34.28 v34.16,34.25 | 74.84,25.74 74.82,25.68 74.77,25.39
  Bottom 0.406: 26.57,25.34 26.51,25.05 | IC2.7 R2.2 | 46.83,26.67 52.92,26.67 | 33.49,29.84 v34.12,30.48 | 59.55,21.78 59.55,18.46 | 63.3,22.22 69.57,22.22
  Bottom 0.61: 29.05,20.32 IC3.16 26.51,20.32 26.51,25.05 | C13.- 18.25,25.97 | 18.25,25.97 25.37,25.95 26.57,25.34 | 18.25,25.97 IC4.8 21.43,29.84 21.43,39.07 | IC2.7 46.83,22.86 46.83,26.67 46.83,27.94 IC2.20 C7.1 33.49,27.94 | 33.49,27.94 32.22,27.94 31.03,28.82 31.02,35.08 28.54,35.01 28.52,37.18 27.13,39.1 21.43,39.07 | 21.43,39.07 C18.1 | 73.43,26.03 69.68,26.03 69.43,25.78 | 73.43,26.03 IC1.20 C4.1 | 69.43,25.78 69.57,25.39 69.57,22.22 | 52.92,26.67 59.55,21.78 | SV1.2 40.48,50.79 34.23,48 34.12,47.6 v34.12,34.28 | 33.49,27.94 33.49,29.84 | 59.55,18.46 60.16,18.41 63.3,18.38 63.3,22.22 | 69.43,25.78 69.45,25.75 | 69.43,25.78 | 69.45,25.75 7805.OUT | 69.45,25.75 69.54,25.66 | 74.82,25.68 73.29,26 74.82,25.68 | 74.82,25.68 76.31,25.37 74.82,25.68 | 74.82,25.68 | 73.43,26.03 74.84,25.74 76.45,25.4
VSS  (via drill 0.6, 0.6 pad 1.42, 0.6 pad 1.68, 0.6 pad 1.78)
  Top 0.406: v89.37,10.79 v89.37,15.38
  Top 0.61: v89.7,20.19 89.78,20.26 v93.91,20.26 v93.91,20.25
  Bottom 0.4: 89.37,10.66 v89.38,10.73 | 88.91,15.37 89.45,15.34 | 88.91,15.37 88.1,15.79 | 88.91,15.37 v89.37,15.38 90,15.3 | 89.75,20.32 v89.7,20.19 | v93.88,20.19 93.81,20.32 v93.91,20.25
  Bottom 0.61: IC1.10 70.95,3.17 70.95,1.27 89.37,1.27 90,1.9 90,5.71 89.37,6.34 89.37,7.62 | 89.37,7.62 D6.C | 89.37,7.62 89.37,10.66 v89.37,10.79 | C5.1 65.9,33.73 66.92,34.75 69.32,34.75 7805.IN | 7805.IN | 7805.IN 71.82,34.63 72.24,34.59 72.61,34.59 74.11,34.62 77.18,34.62 78.46,34.61 80.69,34.61 80.72,28.49 87.97,28.44 87.97,24.25 89.75,24.12 89.75,20.32 90,15.3 | 88.1,15.79 D5.C | 93.99,20.24 SV2.2 | 93.99,20.24 93.98,20.26 | v89.37,15.38 89.55,15.38 89.63,15.31 89.7,15.38 | 93.99,20.24 94.01,20.24 94.01,20.25 v93.91,20.25

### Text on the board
Bottom: 16V~ | LOKPROG | OUT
